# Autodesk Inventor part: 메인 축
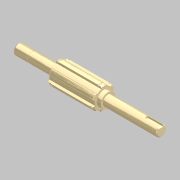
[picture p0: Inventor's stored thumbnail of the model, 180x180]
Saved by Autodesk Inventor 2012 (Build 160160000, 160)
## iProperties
Company: 한국ATC센터
Created: 2014-07
Part Number: 메인 축
Document SubType Name: 모델링
Designer: KYOUNG IL JANG
Mass: 168.566 g
Surface Area: 72.5109 cm^2
Volume: 21.4461 cm^3
Density: 7.86 g/cm^3
Material: 강, 연강
변환 표준: STEP AP214IS
파일 이름: C:\Users\SeoGD\Desktop\?쒗뿕\硫붿씤 異?.stp
전처리기: Build: 253, Release: 2010 SP1 - Date: Wed 07/29/2009
전송 단위: 밀리미터
불확실성: 0.01
Author: KYOUNG IL JANG
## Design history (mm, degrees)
sketch "스케치1"
  geometry: L1 (-69.5, 0)-(69.5, 0); L2 (69.5, 0)-(69.5, 5); L3 (69.5, 5)-(55.5, 5); L4 (55.5, 5)-(55.5, 4.8); L5 (55.5, 4.8)-(54.35, 4.8); L6 (54.35, 4.8)-(54.35, 5); L7 (54.35, 5)-(30.5, 5); L8 (30.5, 5)-(30.5, 9); L9 (30.5, 9)-(-13.5, 9); L10 (-13.5, 9)-(-13.5, 7); L11 (-13.5, 7)-(-17.5, 7); L12 (-17.5, 7)-(-17.5, 5); L13 (-17.5, 5)-(-69.5, 5); L14 (-69.5, 5)-(-69.5, 0); 2 further points
  constraints: 28 end point, 9 parallel, 4 collinear, 2 perpendicular, 1 coincident, 1 horizontal, 1 midpoint
  dimensions: "d2" = 1.15 distance between parallel lines of L6 L4; "d3" = 10 diameter of L3 L1; "d4" = 9.6 diameter of L5 L1; "d6" = 44 distance between parallel lines of L10 L8; "d7" = 4 distance between parallel lines of L12 L10; "d8" = 14 diameter of L11 L1; "d9" = 18 diameter of L9 L1; "d33" = 52 distance from line of L12.end L14; "d37" = 39 distance between parallel lines of L8 L2; "d38" = 14 distance between parallel lines of L2 L4
revolve "회전1" sketch "스케치1" stored, may be unused: angle "d10" = 90 deg
sketch "스케치2"
  geometry: L1 (2.5, 10.712)-(2.5, 8.646); L2 (-2.5, 10.712)-(-2.5, 8.646); A1 r 9 centre (0, 0) between (2.5, 8.646) and (-2.5, 8.646) reference; A2 r 11 centre (0, 0) between (2.5, 10.712) and (-2.5, 10.712); 1 further point
  constraints: 4 end point, 4 point on circle, 2 parallel, 1 centre point, 1 coincident, 1 vertical
  dimensions: "d11" = 22 diameter of A2; "d12" = 5 distance between parallel lines of L1 L2
extrude "돌출1" join sketch "스케치2" stored distance "d13" = 10; taper "d14" = 0 deg
chamfer "모따기1" distance "d15" = 1; stored, may be unused: second distance "d16" = 2, angle "d17" = 45 deg
node "작업 평면1"
node "작업 평면2"
sketch "스케치3"
  geometry: L1 (2.5, 10.712)-(2.5, 10.198); L2 (-2.5, 10.712)-(-2.5, 10.198); A1 r 11 centre (0, 0) between (2.5, 10.712) and (-2.5, 10.712) reference; A2 r 10.5 centre (0, 0) between (2.5, 10.198) and (-2.5, 10.198); 1 further point
  constraints: 4 end point, 2 point on circle, 1 centre point, 1 coincident, 1 parallel, 1 vertical
  dimensions: "d19" = 21 diameter of A2
extrude "돌출2" cut sketch "스케치3" distance "d20" = 1.35; taper "d21" = 0 deg
node "작업 평면3"
sketch "스케치4"
  geometry: L1 (-26, -5)-(-26, 5) reference; L2 (-26, 1.5)-(-12.5, 1.5); L3 (-12.5, -1.5)-(-26, -1.5); A1 r 1.5 centre (-12.5, 0) between (-12.5, -1.5) and (-12.5, 1.5); 2 further points
  constraints: 4 end point, 2 perpendicular, 2 point on circle, 2 point on line, 2 tangent, 1 centre point, 1 horizontal alignment, 1 midpoint
  dimensions: "d25" = 3 distance between parallel lines of L3 L2; "d26" = 15 dimension on A1 L1
extrude "돌출3" cut sketch "스케치4" distance "d27" = 1.8; taper "d28" = 0 deg
chamfer "모따기2" distance "d29" = 1; stored, may be unused: second distance "d30" = 2, angle "d31" = 45 deg
node "솔리드1"
node "솔리드 본체"
node "곡면 본체"
mirror "대칭1"
pattern_circular "원형 패턴1" dims "d23" = 360 deg
node "솔리드2"
other parameters: "d18" = -1.65
